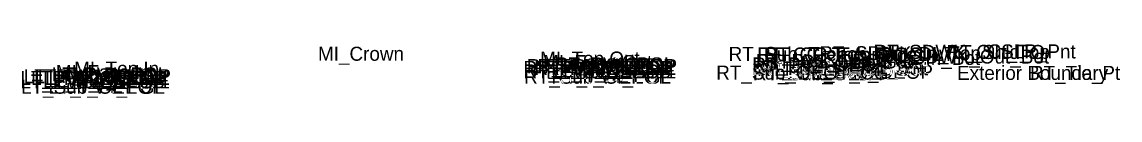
# Model space of a CAD drawing. Extents: x -26 to 6300, y -10 to 9528.
# Drawn here: x 3130.1 to 3207.9, y 4501.2 to 4505.1 of the extents above; entities that cross this region are included whole.
import ezdxf

# ---------------------------------------------------------------- set-up
doc = ezdxf.new("R2010")
doc.units = 0
doc.layers.add('Default', color=7, linetype='Continuous')

msp = doc.modelspace()

# ---------------------------------------------------------------- texts
at = {"layer": 'Default'}
for s, p in [('MI_Crown', (3151.114, 4503.888)), ('RT_Sub_Trench_Out_DLT', (3180.198, 4503.874)), ('RT_SDWK_In_Top', (3186.621, 4503.924)), ('RT_SDWK_Out_Top', (3190.463, 4504.024)), ('RT_Shld_O', (3195.633, 4504.014)), ('CSLP_Pnt', (3198.536, 4504.054)), ('MI_Top Out', (3166.845, 4503.545)), ('MI_Face Out', (3167.057, 4503.295)), ('RT_PV1_PGL', (3167.885, 4503.129)), ('MI_Bot Out', (3168.248, 4503.129)), ('RT_PV2_OEOT', (3181.873, 4503.127)), ('RT_PV1_OEOT', (3182.112, 4503.377)), ('RT_CG_Top_Face', (3182.225, 4503.834)), ('RT_CG_Top_BOC', (3182.694, 4503.834)), ('RT_CG_Top_Gut', (3182.752, 4503.334)), ('RT_SDWK_In_Bot', (3186.87, 4503.59)), ('RT_SDWK_Out_Bot', (3190.712, 4503.69)), ('LT_PV1_PGL', (3132.253, 4502.414)), ('MI_Face In', (3132.551, 4502.58)), ('MI_Bot In', (3133.721, 4502.414)), ('MI_Top In', (3133.839, 4502.83)), ('RT_PV2_OEEOP', (3165.667, 4502.879)), ('RT_PV3_OEEOP', (3165.667, 4502.629)), ('RT_PV1_OEEOP', (3165.907, 4503.004)), ('RT_PV2_IEEOP', (3166.428, 4502.879)), ('RT_PV1_IEEOP', (3166.667, 4503.004)), ('RT_PV2_PGL1', (3167.266, 4502.879)), ('RT_PV3_PGL1', (3167.266, 4502.629)), ('RT_PV2_PGL', (3167.645, 4502.879)), ('RT_Sub_OEOT_CG', (3179.318, 4502.543)), ('RT_PV3_OEOT', (3181.873, 4502.877)), ('RT_Sub_OEOT', (3181.92, 4502.502)), ('RT_CG_Bot_IE', (3182.221, 4502.793)), ('RT_CG1_Shelf_Out', (3182.36, 4502.849)), ('RT_CG_Bot_BOC', (3182.97, 4502.84)), ('RT_Sub_OEOP', (3185.157, 4502.603)), ('Exterior Boundary', (3196.379, 4502.525)), ('RT_Tie_Pt', (3201.542, 4502.525)), ('LT_PV2_OEEOP', (3130.035, 4502.164)), ('LT_PV3_OEEOP', (3130.035, 4501.914)), ('LT_Sub_OEEOP', (3130.082, 4501.539)), ('LT_PV1_OEEOP', (3130.275, 4502.289)), ('LT_PV2_IEEOP', (3130.796, 4502.164)), ('LT_PV1_IEEOP', (3131.035, 4502.289)), ('LT_PV2_PGL1', (3131.635, 4502.164)), ('LT_PV3_PGL1', (3131.635, 4501.914)), ('LT_PV2_PGL', (3132.014, 4502.164)), ('LT_PV4_PGL', (3132.014, 4501.539)), ('RT_Sub_OEEOP', (3165.714, 4502.254)), ('RT_PV4_PGL', (3167.645, 4502.254))]:
    msp.add_text(s, height=1, dxfattribs=at).set_placement(p)

doc.saveas('drawing.dxf')
